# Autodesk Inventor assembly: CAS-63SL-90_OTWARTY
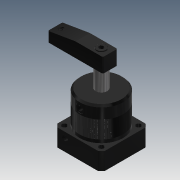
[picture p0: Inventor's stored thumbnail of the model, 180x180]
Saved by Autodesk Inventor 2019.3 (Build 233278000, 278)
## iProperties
Created: 2009-09
Part Number: CAS-63SL-90_OTWARTY
Material: Ogólny
Document SubType Name: Assembly
Designer: CADENGINEERING4
Sending System: PRO/ENGINEER BY PARAMETRIC TECHNOLOGY CORPORATION, 2007170
Preprocessor: PRO/ENGINEER BY PARAMETRIC TECHNOLOGY CORPORATION, 2007170
Title: CAS-63S_ASM
Author: Administrator
Revision Number: 1LAST_VERSION
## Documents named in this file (7)
- D:\Vault_2016\Projekty\STRONA\Pneumatic\Line ; Pipe connecct - type\cas-63s_asm\CAS-63SL-90_OTWARTY.iam
- D:\Vault_2016\Projekty\STRONA\Pneumatic\Line ; Pipe connecct - type\cas-63s_asm\CAS-63BT.ipt
- D:\Vault_2016\Projekty\STRONA\Pneumatic\Line ; Pipe connecct - type\cas-63s_asm\CAS-63SHSG.ipt
- D:\Vault_2016\Projekty\STRONA\Pneumatic\Line ; Pipe connecct - type\cas-63s_asm\CAS-63HG.ipt
- D:\Vault_2016\Projekty\STRONA\Pneumatic\Line ; Pipe connecct - type\cas-63s_asm\M4.ipt
- D:\Vault_2016\Projekty\STRONA\Pneumatic\Line ; Pipe connecct - type\cas-63s_asm\CAS-63SYB.ipt
- D:\Vault_2016\Projekty\STRONA\Pneumatic\Line ; Pipe connecct - type\cas-63s_asm\M10LC.ipt
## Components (11 placed, 11 different names)
1. CAS-63BT_0
2. CAS-63SHSG_1
3. CAS-63HG_2
4. M4_3
5. M4_4
6. M4_5
7. M4_6
8. M4_7
9. M4_8
10. CAS-63SYB_9
11. M10LC_10
